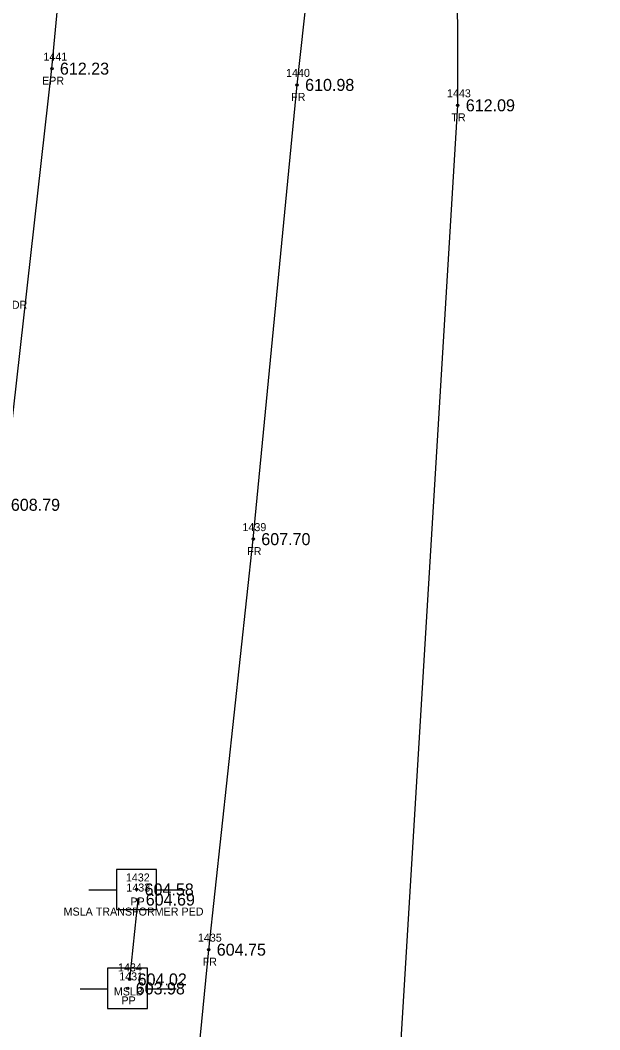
# Model space of a CAD drawing. Extents: x 1694813 to 1696862, y 1086485 to 1091027.
# Drawn here: x 1695838.5 to 1695910.8, y 1089855.4 to 1089981.5 of the extents above; entities that cross this region are included whole.
import ezdxf

# ---------------------------------------------------------------- set-up
doc = ezdxf.new("R2010")
doc.units = 0
for name, color, linetype in [('RD_EX_Fence_Other', 7, 'Continuous'), ('RD_EX_Fence_Other_txCode', 7, 'Continuous'), ('RD_EX_Misc', 7, 'Continuous'), ('RD_EX_Misc_txCode', 7, 'Continuous'), ('RD_EX_Road', 7, 'Continuous'), ('RD_EX_Road_txCode', 7, 'Continuous'), ('RD_EX_TX_Fence_Other_ELEV', 7, 'Continuous'), ('RD_EX_TX_Misc_ELEV', 7, 'Continuous'), ('RD_EX_TX_Road_ELEV', 7, 'Continuous'), ('RD_EX_TX_VEG_ELEV', 7, 'Continuous'), ('RD_EX_UT', 7, 'Continuous'), ('RD_EX_UT_txCode', 7, 'Continuous'), ('RD_EX_VEG', 7, 'Continuous'), ('RD_EX_VEG_txCode', 7, 'Continuous'), ('RD_HC_Survey_ELEV', 7, 'Continuous'), ('RD_HC_txCode', 7, 'Continuous'), ('RD_SMD_Locator', 7, 'Continuous')]:
    doc.layers.add(name, color=color, linetype=linetype)

msp = doc.modelspace()

# ---------------------------------------------------------------- linework, layer by layer
at = {"layer": 'RD_EX_Fence_Other'}
msp.add_lwpolyline([(1695898.78, 1089833.45), (1695859, 1089834.26), (1695862.01, 1089865.39), (1695867.57, 1089916.68), (1695873.04, 1089973.43), (1695877.77, 1090016.67), (1695879.63, 1090038.73)], dxfattribs=at)
at = {"layer": 'RD_EX_Misc'}
msp.add_line((1695853.15, 1089871.65), (1695852.14, 1089861.67), dxfattribs=at)
at = {"layer": 'RD_EX_Road'}
msp.add_lwpolyline([(1695735.35, 1089335.84), (1695728.69, 1089383.6), (1695727.9, 1089434.83), (1695732.68, 1089480.1), (1695743.4, 1089531.84), (1695770.35, 1089628.36), (1695797.63, 1089725.22), (1695809.49, 1089772.37), (1695818.34, 1089811.57), (1695820.65, 1089823.41), (1695822.99, 1089835.26), (1695829.18, 1089869.37), (1695836.32, 1089920.97), (1695842.44, 1089975.46), (1695846.49, 1090018.55), (1695849.32, 1090055.39), (1695850.91, 1090072.92), (1695855.09, 1090117.49), (1695863.53, 1090214.93), (1695872.56, 1090312.44), (1695881.69, 1090410.78), (1695890.45, 1090509.3), (1695899.01, 1090605.4)], dxfattribs=at)
at = {"layer": 'RD_EX_UT'}
for p, q in [((1695855.5, 1089875.42), (1695850.5, 1089875.42)), ((1695850.5, 1089875.42), (1695850.5, 1089870.42)), ((1695855.5, 1089870.42), (1695855.5, 1089875.42)), ((1695847.07, 1089872.85), (1695850.54, 1089872.85)), ((1695855.43, 1089872.85), (1695859.07, 1089872.85)), ((1695850.5, 1089870.42), (1695855.5, 1089870.42)), ((1695854.39, 1089863.06), (1695849.39, 1089863.06)), ((1695849.39, 1089863.06), (1695849.39, 1089858.06)), ((1695854.39, 1089858.06), (1695854.39, 1089863.06)), ((1695845.96, 1089860.5), (1695849.43, 1089860.5)), ((1695854.32, 1089860.5), (1695857.96, 1089860.5)), ((1695849.39, 1089858.06), (1695854.39, 1089858.06))]:
    msp.add_line(p, q, dxfattribs=at)
at = {"layer": 'RD_EX_VEG'}
msp.add_lwpolyline([(1695885.82, 1089850.68), (1695893.09, 1089970.88), (1695893.02, 1090013.82), (1695904.28, 1090114.68), (1695866.77, 1090153.16), (1695876.29, 1090212.72), (1695880.67, 1090311.3), (1695888, 1090410.55), (1695898.84, 1090510.09), (1695910.81, 1090607.5)], dxfattribs=at)
at = {"layer": 'RD_SMD_Locator'}
for centre in [(1695842.44, 1089975.46), (1695873.04, 1089973.43), (1695893.09, 1089970.88), (1695867.57, 1089916.68), (1695853.01, 1089872.91), (1695853.15, 1089871.65), (1695862.01, 1089865.39), (1695852.14, 1089861.67), (1695851.9, 1089860.55)]:
    msp.add_circle(centre, 0.15, dxfattribs=at)

# ---------------------------------------------------------------- texts
at = {"layer": 'RD_EX_Fence_Other_txCode'}
for s, p in [('1440', (1695871.66, 1089974.43)), ('FR', (1695872.29, 1089971.43)), ('1439', (1695866.22, 1089917.68)), ('FR', (1695866.81, 1089914.68)), ('1435', (1695860.66, 1089866.39)), ('FR', (1695861.25, 1089863.39))]:
    msp.add_text(s, height=1, dxfattribs=at).set_placement(p)
at = {"layer": 'RD_EX_Misc_txCode'}
for s, p in [('1433', (1695851.73, 1089872.65)), ('MSLA TRANSFORMER PED', (1695843.9, 1089869.65)), ('1434', (1695850.69, 1089862.67)), ('MSLB', (1695850.17, 1089859.67))]:
    msp.add_text(s, height=1, dxfattribs=at).set_placement(p)
at = {"layer": 'RD_EX_Road_txCode'}
for s, p in [('1441', (1695841.38, 1089976.46)), ('EPR', (1695841.21, 1089973.46))]:
    msp.add_text(s, height=1, dxfattribs=at).set_placement(p)
at = {"layer": 'RD_EX_TX_Fence_Other_ELEV'}
for s, p in [('610.98', (1695874.04, 1089972.68)), ('607.70', (1695868.57, 1089915.93)), ('604.75', (1695863.01, 1089864.64))]:
    msp.add_text(s, height=1.5, dxfattribs=at).set_placement(p)
at = {"layer": 'RD_EX_TX_Misc_ELEV'}
for s, p in [('604.69', (1695854.15, 1089870.9)), ('604.02', (1695853.14, 1089860.92))]:
    msp.add_text(s, height=1.5, dxfattribs=at).set_placement(p)
at = {"layer": 'RD_EX_TX_Road_ELEV'}
for s, p in [('612.23', (1695843.44, 1089974.71)), ('608.79', (1695837.32, 1089920.22))]:
    msp.add_text(s, height=1.5, dxfattribs=at).set_placement(p)
at = {"layer": 'RD_EX_TX_VEG_ELEV'}
msp.add_text('612.09', height=1.5, dxfattribs=at).set_placement((1695894.09, 1089970.13))
at = {"layer": 'RD_EX_UT_txCode'}
for s, p in [('1432', (1695851.67, 1089873.91)), ('PP', (1695852.23, 1089870.91)), ('1431', (1695850.84, 1089861.55)), ('PP', (1695851.12, 1089858.55))]:
    msp.add_text(s, height=1, dxfattribs=at).set_placement(p)
at = {"layer": 'RD_EX_VEG_txCode'}
for s, p in [('1443', (1695891.74, 1089971.88)), ('TR', (1695892.29, 1089968.88))]:
    msp.add_text(s, height=1, dxfattribs=at).set_placement(p)
at = {"layer": 'RD_HC_Survey_ELEV'}
for s, p in [('604.58', (1695854.01, 1089872.16)), ('603.98', (1695852.9, 1089859.8))]:
    msp.add_text(s, height=1.5, dxfattribs=at).set_placement(p)
at = {"layer": 'RD_HC_txCode'}
msp.add_text('POT (10+00.00)NETTY KATHERINE DR', height=1, dxfattribs=at).set_placement((1695815.04, 1089945.46))

doc.saveas('drawing.dxf')
